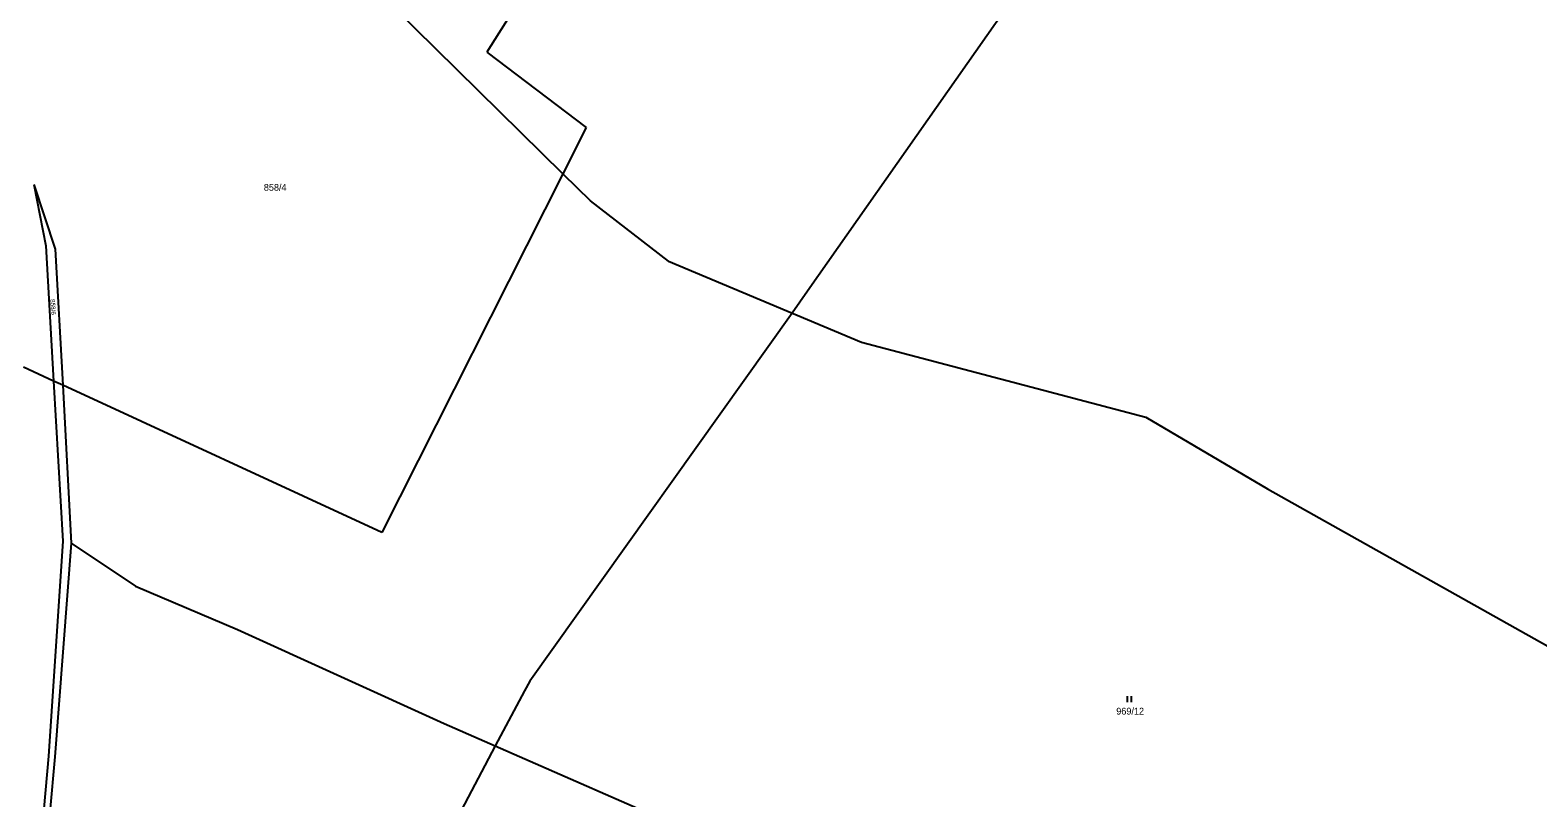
# Model space of a CAD drawing. Extents: x -547623 to -538651, y -1096714 to -1086522.
# Drawn here: x -542783.5 to -542406.3, y -1094026.7 to -1093834.7 of the extents above; entities that cross this region are included whole.
import ezdxf

# ---------------------------------------------------------------- set-up
doc = ezdxf.new("R2010")
doc.units = 0
for name, color, linetype in [('Vrstva 1', 7, 'Continuous'), ('Vrstva 25', 7, 'Continuous'), ('Vrstva 52', 7, 'Continuous'), ('Vrstva 86', 7, 'Continuous')]:
    doc.layers.add(name, color=color, linetype=linetype)

msp = doc.modelspace()

# ---------------------------------------------------------------- linework, layer by layer
at = {"layer": 'Vrstva 1'}
for points in [[(-542627.69, -1093774.4), (-542669.26, -1093840.14)], [(-542697.93, -1093823.54), (-542650.21, -1093870.59)], [(-542669.26, -1093840.14), (-542644.39, -1093859.04)], [(-542644.39, -1093859.04), (-542650.21, -1093870.59)], [(-542650.21, -1093870.59), (-542695.46, -1093960.33)], [(-542650.21, -1093870.59), (-542643.32, -1093877.35)], [(-542782.56, -1093873.24), (-542779.51, -1093888.63)], [(-542782.56, -1093873.24), (-542777.17, -1093889.43)], [(-542623.82, -1093892.44), (-542643.32, -1093877.35)], [(-542779.51, -1093888.63), (-542777.59, -1093922.47)], [(-542777.17, -1093889.43), (-542775.32, -1093923.52)], [(-542623.82, -1093892.44), (-542575.53, -1093912.72)], [(-542575.53, -1093912.72), (-542504.37, -1093931.52)], [(-542777.59, -1093922.47), (-542785.12, -1093919)], [(-542775.32, -1093923.52), (-542777.59, -1093922.47)], [(-542777.59, -1093922.47), (-542775.32, -1093962.55)], [(-542695.46, -1093960.33), (-542775.32, -1093923.52)], [(-542775.32, -1093923.52), (-542773.22, -1093962.98)], [(-542504.37, -1093931.52), (-542473.97, -1093949.46)], [(-542473.97, -1093949.46), (-542369.83, -1094007.85)], [(-542775.32, -1093962.55), (-542778.9, -1094016.32)], [(-542773.22, -1093962.98), (-542777.3, -1094016.49)], [(-542773.22, -1093962.98), (-542757.13, -1093973.81)], [(-542757.13, -1093973.81), (-542731.56, -1093984.63)], [(-542731.56, -1093984.63), (-542679.92, -1094008.12)], [(-542679.92, -1094008.12), (-542605.24, -1094040.82)], [(-542778.9, -1094016.32), (-542782.89, -1094061.19)], [(-542777.3, -1094016.49), (-542781.01, -1094058)]]:
    msp.add_lwpolyline(points, dxfattribs=at)
at = {"layer": 'Vrstva 25'}
for p, q in [((-542508.97, -1094002.83), (-542508.97, -1094001.33)), ((-542507.97, -1094002.83), (-542507.97, -1094001.33))]:
    msp.add_line(p, q, dxfattribs=at)
at = {"layer": 'Vrstva 52'}
msp.add_lwpolyline([(-542422.65, -1093441.62), (-542422.36, -1093480.32), (-542422, -1093529), (-542435.5, -1093605.5), (-542441.52, -1093627.84), (-542449.2, -1093656.37), (-542453, -1093670.5), (-542474, -1093727), (-542500, -1093771.12), (-542507, -1093783), (-542589, -1093900), (-542592.87, -1093905.44), (-542658.5, -1093997.5), (-542659.82, -1094000), (-542667.1, -1094013.74), (-542676.5, -1094031.5), (-542688.5, -1094055), (-542698.58, -1094092.56), (-542708.5, -1094129.5), (-542723.51, -1094211.55), (-542724.31, -1094215.92), (-542746, -1094334.5), (-542748.24, -1094343.37)], dxfattribs=at)

# ---------------------------------------------------------------- texts
at = {"layer": 'Vrstva 86'}
for s, p in [('858/4', (-542725.01, -1093874.84)), ('969/12', (-542511.78, -1094005.9))]:
    msp.add_text(s, height=1.7, dxfattribs=at).set_placement(p)
msp.add_text('858/6', height=1.14, rotation=273.9125, dxfattribs=at).set_placement((-542778.42, -1093902))

doc.saveas('drawing.dxf')
